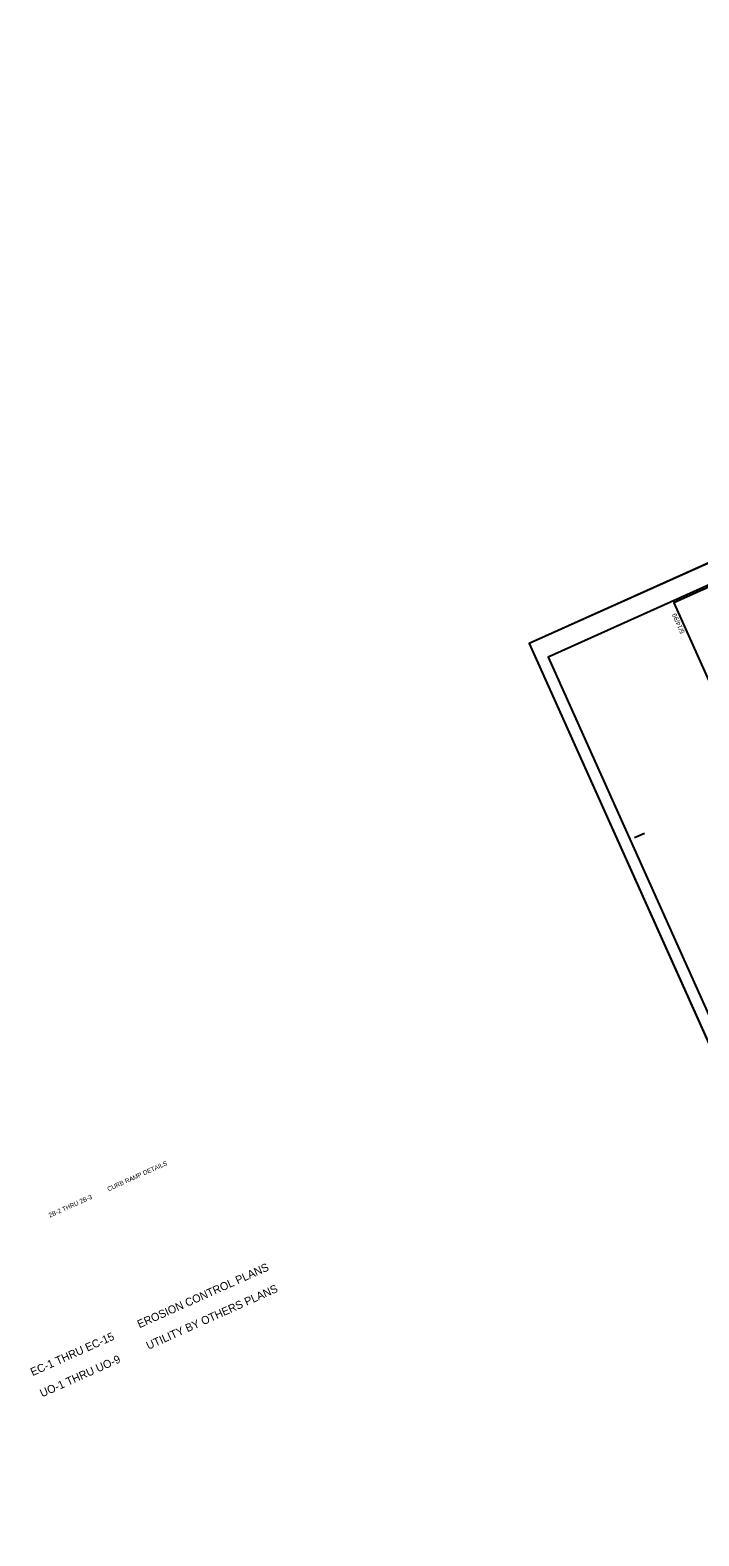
# Model space of a CAD drawing. Extents: x 553377 to 556641, y 502653 to 504402.
# Drawn here: x 553377 to 554129, y 502653 to 504347 of the extents above; entities that cross this region are included whole.
import ezdxf

# ---------------------------------------------------------------- set-up
doc = ezdxf.new("R2010")
doc.units = 0
for name, color, linetype in [('Prop Dimension Text', 7, 'Continuous'), ('Prop Horizontal Alignment Curve and Spiral Data', 7, 'Continuous'), ('Sheet Border Standard 30in CELL', 7, 'Continuous'), ('Sheet Cutting Line CELL', 7, 'Continuous'), ('Sheet Plot Border Inside CELL', 7, 'Continuous'), ('Sheet Plot Border Outside CELL', 7, 'Continuous')]:
    doc.layers.add(name, color=color, linetype=linetype)

msp = doc.modelspace()

# ---------------------------------------------------------------- linework, layer by layer
at = {"layer": 'Sheet Border Standard 30in CELL'}
for p, q in [((554102.1, 503702.8), (554102.1, 503702.8)), ((554056.9, 503438.6), (554068.3, 503443.7))]:
    msp.add_line(p, q, dxfattribs=at)
msp.add_lwpolyline([(555469.6, 504316.8), (554101.2, 503702.4), (554531.3, 502744.5), (555899.7, 503359)], close=True, dxfattribs=at)
at = {"layer": 'Sheet Cutting Line CELL'}
for p, q in [((555474.9, 504346.6), (553938.6, 503656.8)), ((553938.6, 503656.8), (554389.2, 502653.3))]:
    msp.add_line(p, q, dxfattribs=at)
at = {"layer": 'Sheet Plot Border Inside CELL'}
msp.add_lwpolyline([(555480, 504324.3), (553959.7, 503641.6), (554391.9, 502679.1), (555912.2, 503361.8)], close=True, dxfattribs=at)
at = {"layer": 'Sheet Plot Border Outside CELL'}
msp.add_lwpolyline([(555474.9, 504346.6), (553938.6, 503656.8), (554389.2, 502653.3), (555925.5, 503343.1)], close=True, dxfattribs=at)

# ---------------------------------------------------------------- texts
at = {"layer": 'Prop Dimension Text'}
msp.add_text('2B-2 THRU 2B-3          CURB RAMP DETAILS', height=5.063, rotation=24.1169, dxfattribs=at).set_placement((553399.1, 503011.2))
at = {"layer": 'Prop Horizontal Alignment Curve and Spiral Data'}
for s, p in [('EC-1 THRU EC-15         EROSION CONTROL PLANS', (553379.7, 502832.9)), ('UO-1 THRU UO-9          UTILITY BY OTHERS PLANS', (553390.4, 502809))]:
    msp.add_text(s, height=9, rotation=24.1169, dxfattribs=at).set_placement(p)
at = {"layer": 'Sheet Border Standard 30in CELL'}
msp.add_text('5/14/99', height=5.25, rotation=114.1816, dxfattribs=at).set_placement((554113.6, 503669.4))

doc.saveas('drawing.dxf')
